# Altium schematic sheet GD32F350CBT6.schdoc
size 127 x 101 mm
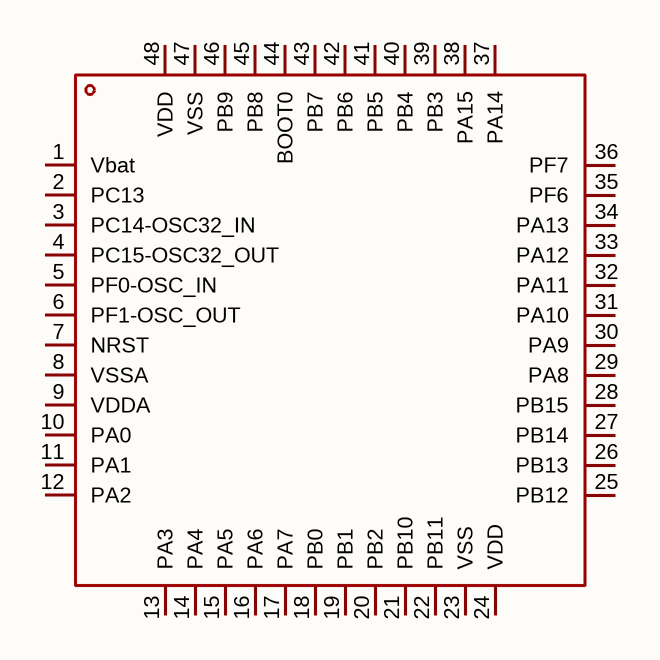
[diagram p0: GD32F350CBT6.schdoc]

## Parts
U?  gd32f350cbt6  [LQFP-48_L7.0-W7.0-P0.50-LS9.0-BL]  (value not drawn)

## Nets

Not connected (* = marked no-connect by the designer): U? 1(Vbat) 2(PC13) 3(PC14-OSC32_IN) 4(PC15-OSC32_OUT) 5(PF0-OSC_IN) 6(PF1-OSC_OUT) 7(NRST) 8(VSSA) 9(VDDA) 10(PA0) 11(PA1) 12(PA2) 13(PA3) 14(PA4) 15(PA5) 16(PA6) 17(PA7) 18(PB0) 19(PB1) 20(PB2) 21(PB10) 22(PB11) 23(VSS) 24(VDD) 25(PB12) 26(PB13) 27(PB14) 28(PB15) 29(PA8) 30(PA9) 31(PA10) 32(PA11) 33(PA12) 34(PA13) 35(PF6) 36(PF7) 37(PA14) 38(PA15) 39(PB3) 40(PB4) 41(PB5) 42(PB6) 43(PB7) 44(BOOT0) 45(PB8) 46(PB9) 47(VSS) 48(VDD)

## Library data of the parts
U? = gd32f350cbt6: CPU内核:ARM Cortex-M4;CPU最大主频:108MHz;; Manufacturer: GigaDevice(兆易创新); AddInBom: yes; ModelId: 093be70396ff421eb2cdb946d5311efc; ModelName: LQFP-48_L7.0-W7.0-H1.4-LS9.0-P0.50; ModelTransform: 354.331,354.331,0,0,0,0,0,0,0; CPU Maximum Speed: 108MHz; Program Storage Size: 64KB; Program Memory Type: FLASH; Number of I/O: 39; ADC (Bit): 12bit; Voltage - Supply: 2.6V~3.6V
